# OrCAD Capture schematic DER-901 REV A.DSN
size Custom; title: DER-801 Rev B
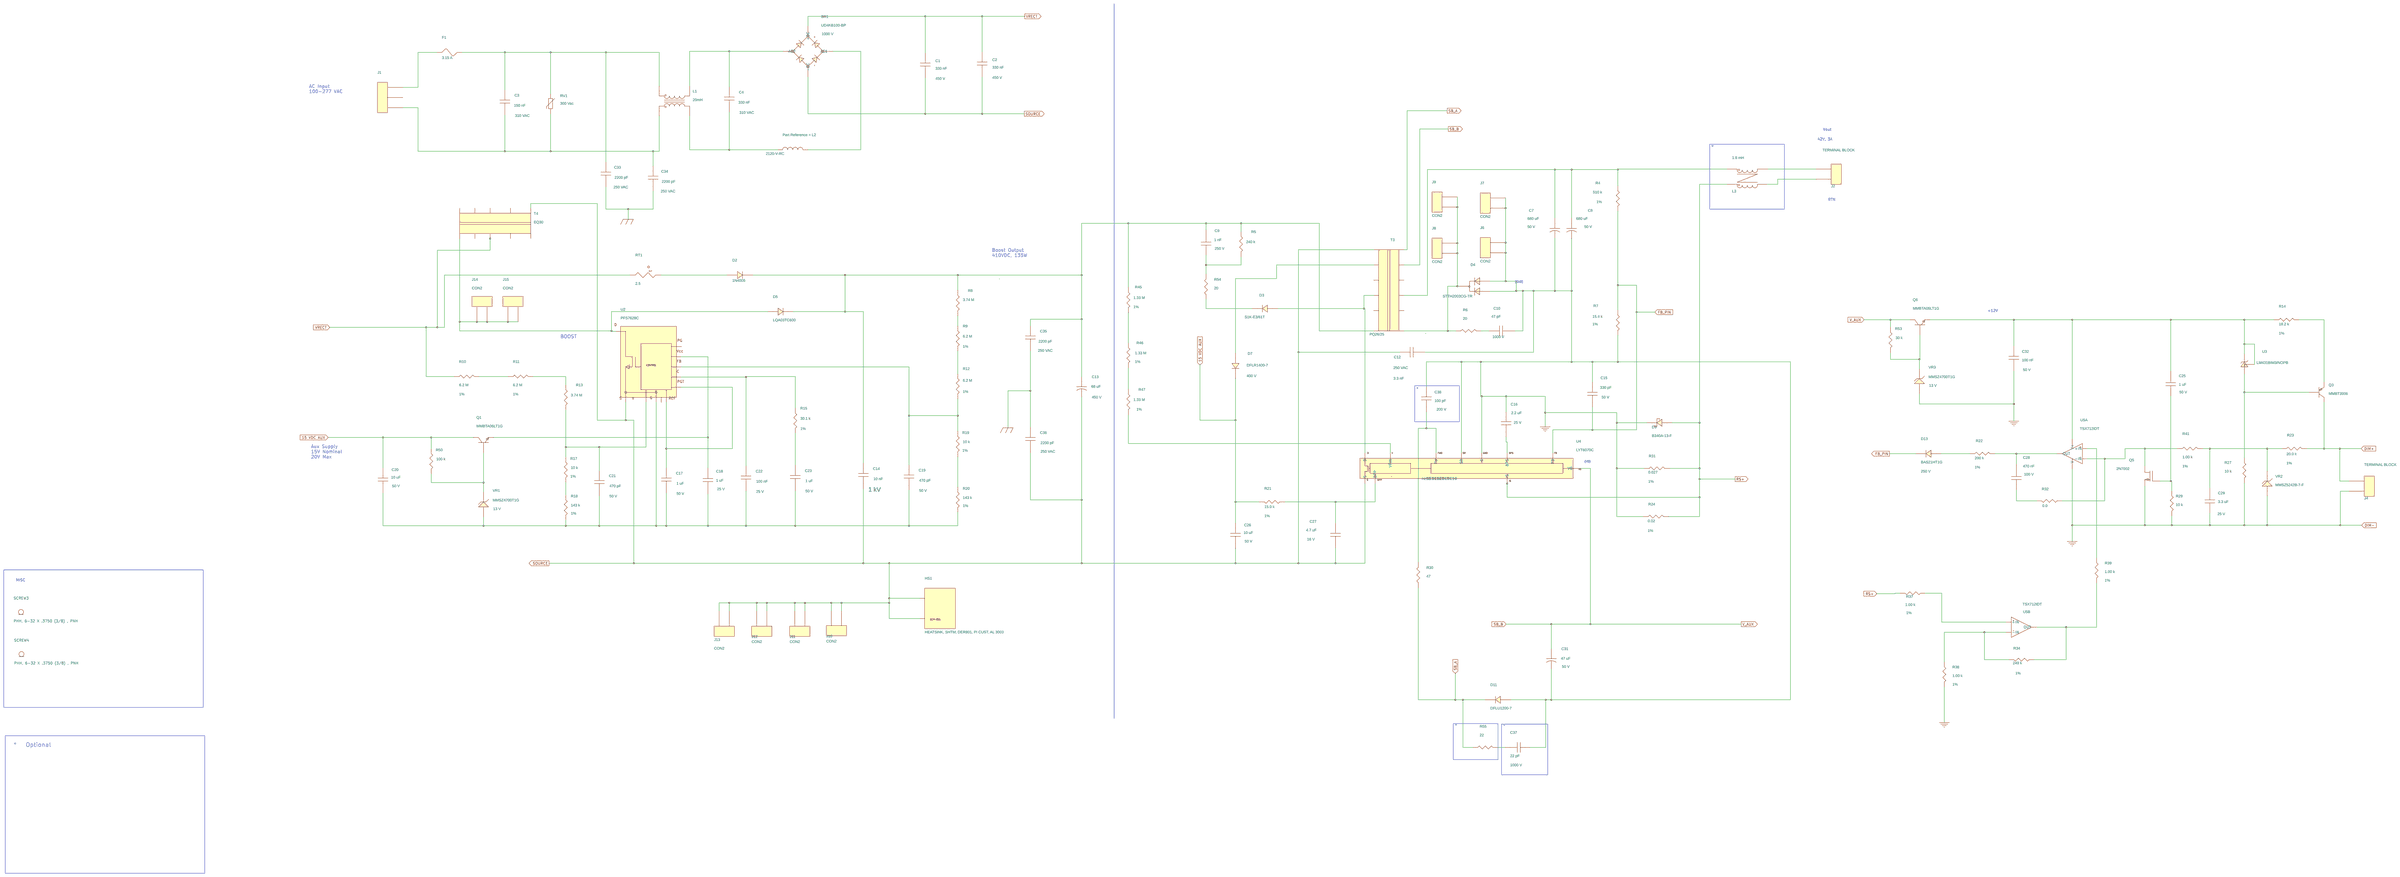
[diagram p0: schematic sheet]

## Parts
BR1  UD4KB100-BP  [pidaxbridgeD3K]
C1  330 nF  [pi_np_caprad512x299ls394d040]
C2  330 nF  [pi_np_caprad512x299ls394d040]
C3  150 nF  [pinpxcaprad720x240590040]
C4  330 nF  [pinpxcaprad710x315590046]
C7  680 uF  [pipolcapclyd500ls200040]
C8  680 uF  [pipolcapclyd500ls200040]
C9  1 nF  [pismc0805]
C10  47 pF  [pismc1206]
C12  3.3 nF  [pinpycaprad540x290ls400040]
C13  68 uF  [pipolcapclyd710ls300040]
C14  10 nF  [pi_np_cap250x200ls170d030]
C15  330 pF  [pismc0603]
C16  2.2 uF  [pismc1206]
C17  1 uF  [pismc0805]
C18  1 uF  [pismc0805]
C19  470 pF  [pismc0805]
C20  10 uF  [pismc1206]
C21  470 pF  [pismc0805]
C22  100 nF  [pismc0805]
C23  1 uF  [pismc0805]
C25  1 uF  [pismc0805]
C26  10 uF  [pismc1206]
C27  4.7 uF  [pismc0805]
C28  470 nF  [pismc1206]
C29  3.3 uF  [pismc0805]
C31  47 uF  [pipolcapcyld250ls100030]
C32  100 nF  [pismc0805]
C33  2200 pF  [pinpcaprad9p0D10p0LS030]
C34  2200 pF  [pinpcaprad9p0D10p0LS030]
C35  2200 pF  [pinpcaprad9p0D10p0LS030]
C36  2200 pF  [pinpcaprad9p0D10p0LS030]
C37  22 pF  [pismc0805]
C38  100 pF  [pismc0805]
D2  1N4006  [pidv200x110x040do41]
D3  S1K-E3/61T  [pismdo214ac12]
D4  STTH2003CG-TR  [pismdd2pak]
D5  LQA03TC600  [pidvt0220acreva]
D7  DFLR1400-7  [pismddflr120012]
D9  B340A-13-F  [pismdo214ac12]
D11  DFLU1200-7  [pismddflr120012]
D13  BAS21HT1G  [pismsod323]
F1  3.15 A  [pi_rst_microfuse]
HS1  HEATSINK, SHTM, DER801, PI CUST, AL 3003  [PI_HS_2P_DER801]
J1  TERMINAL BLOCK  [pi_term_block_3pin]
J2  TERMINAL BLOCK  [pi_term_block_2pin_ls200]
J4  TERMINAL BLOCK  [pi_term_block_2pin_ls200]
J6  CON2  [pi_conn_qc_tab_2pin_ls200]
J7  CON2  [pi_conn_qc_tab_2pin_ls200]
J8  CON2  [pi_conn_qc_tab_2pin_ls200]
J9  CON2  [pi_conn_qc_tab_2pin_ls200]
J10  CON2  [pi_conn_qc_tab_2pin_ls200]
J11  CON2  [pi_conn_qc_tab_2pin_ls200]
J12  CON2  [pi_conn_qc_tab_2pin_ls200]
J13  CON2  [pi_conn_qc_tab_2pin_ls200]
J14  CON2  [pi_conn_qc_tab_2pin_ls200]
J15  CON2  [pi_conn_qc_tab_2pin_ls200]
L1  20mH  [pi_ind_4p_690x512ls300x200d055]
L2  2120-V-RC  [pi_toroid_2p_350x860_ls330_d038]
L3  1.8 mH  [pi_coil_16x8_LS8x7p5]
Q1  MMBTA06LT1G  [pismsot23123_1]
Q3  MMBT3906  [pismsot23123_1]
Q5  2N7002  [pismsot23123_1]
Q6  MMBTA06LT1G  [pismsot23123_1]
R4  510 k  [pismr0805]
R5  240 k  [pismr1206]
R6  20  [pismr1206]
R7  15.4 k  [pismr0805]
R8  3.74 M  [pismr1206]
R9  6.2 M  [pismr1206]
R10  6.2 M  [pismr1206]
R11  6.2 M  [pismr1206]
R12  6.2 M  [pismr1206]
R13  3.74 M  [pismr1206]
R14  18.2 k  [pismr0805]
R15  30.1 k  [pismr0805]
R17  10 k  [pismr0805]
R18  143 k  [pismr0805]
R19  10 k  [pismr0805]
R20  143 k  [pismr0805]
R21  15.0 k  [pismr1206]
R22  200 k  [pismr0805]
R23  20.0 k  [pismr1206]
R24  0.02  [pismr0805]
R27  10 k  [pismr0805]
R29  10 k  [pismr0805]
R30  47  [pismr1206]
R31  0.027  [pismr1206]
R32  0.0  [pismr0805]
R34  249 k  [pismr0805]
R37  1.00 k  [pismr0805]
R38  1.00 k  [pismr0805]
R39  1.00 k  [pismr0805]
R41  1.00 k  [pismr0805]
R45  1.33 M  [pismr1206]
R46  1.33 M  [pismr1206]
R47  1.33 M  [pismr1206]
R50  100 k  [pismr0805]
R53  30 k  [pismr0805]
R54  20  [pismr1206]
R55  22  [pismr0805]
RT1  2.5  [pi_rad150x300ls200d030]
RV1  300 Vac  [pidisc350x225ls240x140040]
SCREW3  PHH, 6-32 X .3750 (3/8) , PNH
SCREW4  PHH, 6-32 X .3750 (3/8) , PNH
T3  PQ26/25  [pibobbinpq262512p]
T4  EQ30  [pi_bobbin_eq30_v_10p]
U2  PFS7628C  [PI_IC_INSOP24B]
U3  LM431BIM3/NOPB  [pismsot23123]
U4  LYT6070C  [pi_ic_insop_24d]
U5  TSX712IDT  [pismso8]  (sections A,B)
VR1  MMSZ4700T1G  [pi_sm_sod-123_12]
VR2  MMSZ5242B-7-F  [pi_sm_sod-123_12]
VR3  MMSZ4700T1G  [pi_sm_sod-123_12]

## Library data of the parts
BR1 = DISCRETE_BRIDGE_+~~-: ALT_SYMBOLS: pidaxbridgeD3K_horz; Disp_Voltage: 1000 V; FPLIST: pidaxbridgeD3K,pidaxbridgeD3K_horz; Part Number: 15-01213-00
C1 C2 = CAP_NP: ALT_SYMBOLS: pi_np_caprad512x299ls394d040_h; Disp_Voltage: 450 V; FPLIST: pi_np_caprad512x299ls394d040,pi_np_caprad512x299ls394d040_h; Part Number: 20-00973-00; Voltage: 450 V
C3 = CAP_NP: Disp_Voltage: 310 VAC; Part Number: 20-01052-00; Voltage: 310 VAC
C4 = CAP_NP: Disp_Voltage: 310 VAC; Part Number: 20-08604-00; Voltage: 310 VAC
C7 C8 = CAP_POL: ALT_SYMBOLS: pipolcapclyd500ls2000401000lh; COMPGROUP: 3; Disp_Voltage: 50 V; FPLIST: pipolcapclyd500ls200040,pipolcapclyd500ls2000401000lh; Part Number: 20-00710-00; Voltage: 50 V
C9 = CAP_NP: Disp_Voltage: 250 V; Part Number: 20-00736-00; Voltage: 250 V
C10 = CAP_NP: Disp_Voltage: 1000 V; PCB Editor PCBFP: pismc0603; Part Number: 20-08683-00; Voltage: 1000 V
C12 = CAP_NP: ALT_SYMBOLS: pinpycaprad540x290ls400040h; COMPGROUP: 3; Disp_Voltage: 250 VAC; FPLIST: pinpycaprad540x290ls400040,pinpycaprad540x290ls400040h; Part Number: 20-00377-00; Voltage: 250 VAC
C13 = CAP_POL: ALT_SYMBOLS: pi_cap_cly_d710_ls300_040_1000h; Disp_Voltage: 450 V; FPLIST: pipolcapclyd710ls300040,pi_cap_cly_d710_ls300_040_1000h; Part Number: 20-09153-00; Voltage: 450 V
C14 = CAP_NP: Disp_Voltage: 1 kV; Part Number: 20-00894-00; Voltage: 1 kV
C15 = CAP_NP: Disp_Voltage: 50 V; Part Number: 20-08676-00; Voltage: 50 V
C16 = CAP_NP: Disp_Voltage: 25 V; Part Number: 20-01034-00; Voltage: 25 V
C17 C23 = CAP_NP: Disp_Voltage: 50 V; Part Number: 20-09156-00; Voltage: 50 V
C18 = CAP_NP: Disp_Voltage: 25 V; Part Number: 20-09171-00; Voltage: 25 V
C19 C21 = CAP_NP: Disp_Voltage: 50 V; Part Number: 20-00205-00; Voltage: 50 V
C20 C26 = CAP_NP: ALT_SYMBOLS: pismc1206_1; Disp_Voltage: 50 V; FPLIST: pismc1206,pismc1206_1; Part Number: 20-08995-00; Voltage: 50 V
C22 = CAP_NP: Disp_Voltage: 25 V; Part Number: 20-08599-00; Voltage: 25 V
C25 = CAP_NP: Disp_Voltage: 50 V; Part Number: 20-09146-00; Voltage: 50 V
C27 = CAP_NP: Disp_Voltage: 16 V; Part Number: 20-09166-00; Voltage: 16 V
C28 = CAP_NP: Disp_Voltage: 100 V; Part Number: 20-00583-00; Voltage: 100 V
C29 = CAP_NP: Disp_Voltage: 25 V; Part Number: 20-01041-00; Voltage: 25 V
C31 = CAP_POL: ALT_SYMBOLS: pipolcapcyld250ls100030h; Disp_Voltage: 50 V; FPLIST: pipolcapcyld250ls100030,pipolcapcyld250ls100030h; Part Number: 20-01044-00; Voltage: 50 V
C32 = CAP_NP: Disp_Voltage: 50 V; Part Number: 20-00904-00; Voltage: 50 V
C33-C36 = CAP_NP: Disp_Voltage: 250 VAC; Part Number: 20-09158-00; Voltage: 250 VAC
C37 = CAP_NP: Disp_Voltage: 1000 V; PCB Editor PCBFP: pismc0603; Part Number: 20-08905-00; Voltage: 1000 V
C38 = CAP_NP: Disp_Voltage: 200 V; PCB Editor PCBFP: pismc0603; Part Number: 20-00760-00; Voltage: 200 V
D2 = DIODE: ALT_SYMBOLS: pidax475x125040do41,pidv200x110x040do41wbead,pidax390x125040do41; FPLIST: pidv200x110x040do41,pidax475x125040do41,pidv200x110x040do41wbead,pidax390x125040do41; Part Number: 15-00629-00
D3 = DIODE: Part Number: 15-01053-00
D4 = D_DUAL_CK_AKA: Part Number: 15-01586-00
D5 = DIODE: Part Number: 15-00834-00
D7 = DIODE: COMPGROUP: 1; Disp_Voltage: 400 V; Part Number: 15-01310-00
D9 = DIODE_SCHOTTKY: Part Number: 15-01172-00
D11 = DIODE: Part Number: 15-01043-00
D13 = DIODE: ALT_SYMBOLS: pismsod323_1; Disp_Voltage: 250 V; FPLIST: pismsod323,pismsod323_1; Part Number: 15-01247-00
F1 = FUSE: ALT_SYMBOLS: pirstmicrofusehoz; FPLIST: pi_rst_microfuse,pirstmicrofusehoz; Part Number: 40-00020-00
HS1 = hs_2P_DER801: Part Number: 61-00245-00
J1 = CON3: Part Number: 35-00175-00
J2 J4 = CON2: Part Number: 35-00277-00
J6-J15 = CON2: Part Number: 35-00281-00
L1 = INDUCTOR_4P_revD: ALT_SYMBOLS: pi_4p_700x400d055_horiz; FPLIST: pi_ind_4p_690x512ls300x200d055,pi_4p_700x400d055_horiz; Part Number: 30-04099-00
L2 = INDUCTOR: ALT_SYMBOLS: pi_2p_700x400d055_horiz; FPLIST: pi_toroid_2p_350x860_ls330_d038,pi_2p_700x400d055_horiz; Part Number: 32-00224-00
L3 = TORRID_4P_14_23: Part Number: 32-00375-00
Q1 Q6 = NPN_BEC: Part Number: 55-00072-00
Q3 = PNP_BEC: Part Number: 55-00049-00
Q5 = FET_N_GSD: Part Number: 50-00103-00
R4 = R: Disp_Tol: 1%; Part Number: 05-03469-00
R5 = R: Part Number: 05-01409-00
R6 R54 = R: Part Number: 05-01311-00
R7 = R: Disp_Tol: 1%; Part Number: 05-00702-00
R8 R13 = R: Part Number: 05-05572-00
R9-R12 = R: Disp_Tol: 1%; Part Number: 05-05567-00
R14 = R: Disp_Tol: 1%; Part Number: 05-00709-00
R15 = R: Disp_Tol: 1%; Part Number: 05-00730-00
R17 R19 = R: Disp_Tol: 1%; Part Number: 05-00684-00
R18 R20 = R: Disp_Tol: 1%; Part Number: 05-00795-00
R21 = R: Disp_Tol: 1%; Part Number: 05-00306-00
R22 = R: Disp_Tol: 1%; Part Number: 05-00809-00
R23 = R: Disp_Tol: 1%; Part Number: 05-00318-00
R24 = R: Disp_Tol: 1%; Part Number: 05-05450-00
R27 R29 = R: Part Number: 05-01543-00
R30 = R: Part Number: 05-01320-00
R31 = R: Disp_Tol: 1%; Part Number: 05-06531-00
R32 = R: ALT_SYMBOLS: pismr0805_1; FPLIST: pismr0805,pismr0805_1; Part Number: 05-03159-00
R34 = R: Disp_Tol: 1%; Part Number: 05-00818-00
R37-R39 R41 = R: Disp_Tol: 1%; Part Number: 05-03310-00
R45-R47 = R: Disp_Tol: 1%; Part Number: 05-05444-00
R50 = R: Part Number: 05-01567-00
R53 = R: Part Number: 05-01554-00
R55 = R: Part Number: 05-01479-00
RT1 = THERMISTOR: ALT_SYMBOLS: pirad400x300ls200040_h; FPLIST: pi_rad150x300ls200d030,pirad400x300ls200040_h; Part Number: 90-00040-00
RV1 = VARISTOR: Part Number: 85-00031-00
SCREW3 SCREW4 = SCR_6-32: Part Number: 75-00009-00
T3 = BPQ26_25_12P_GENERIC: Part Number: 25-00055-00
T4 = BEQ30_10P_GENERIC: Part Number: 25-00074-00
U2 = HIPERPFS-4-inSOP24B_0: Part Number: 10-01069-00
U3 = TL431_SOT-23_CAR: Part Number: 45-00232-00
U4 = LYT6: Part Number: 10-01225-00
U5 = TSX712IDT: Part Number: 45-00514-00
VR1 VR3 = DIODE_ZENER: Disp_Voltage: 13 V; Part Number: 15-01046-00
VR2 = DIODE_ZENER: Part Number: 15-01090-00

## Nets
GND: C7.2 C8.2 C10.2 C12.2 C15.1 C16.1 C29.1 C31.2 C32.2 C37.1 C38.1 D4.1(A1) D4.3(A2) D9.1 D11.2 J4.1 J6.1 J6.2 J7.1 J7.2 Q5.2(S) R7.2 R24.1 R27.2 R29.2 R31.1 R38.2 U4.2(G) U4.5(SR) U5.4(V-) VR2.2 VR3.2
GND_EARTH: C33.2 C34.2 C35.2 C36.1
15 VDC AUX: C20.1 C26.1 D7.1 Q1.3(COLLECTOR) R21.1 R50.1
DIM+: J4.2 Q3.3(COLLECTOR) R23.2
FB_PIN: C15.2 D13.1 R4.2 R7.1 U4.3(FB)
NC8: U4.8(NC8)
NC9: U4.9(NC9)
NC10: U4.10(NC10)
NC11: U4.11(NC11)
NC12: U4.12(NC12)
NC15: U4.15(nc15)
RS+: D9.2 L3.2 R24.2 R31.2 R37.2 U4.1(IS)
SB_A: D11.1 R30.1 R55.2 T3.7
SB_B: C31.1 Q6.3(COLLECTOR) R53.1 T3.8 U4.6(VO)
SOURCE: BR1.4(-DC) C1.2 C2.2 C12.1 C13.2 C14.2 C26.2 C27.2 C36.2 HS1.1 HS1.2 J10.1 J10.2 J11.1 J11.2 J12.1 J12.2 J13.1 J13.2 T3.6 T4.6 U2.24(S) U4.16(S)
VRECT: BR1.1(+DC) C1.1 C2.1 R10.1 RT1.1 T4.3
N11474046: F1.1 J1.3
N11474062: C3.1 C33.1 F1.2 L1.4 RV1.1
N11474114: BR1.3(AC2) C4.1 L1.3
N11474138: BR1.2(AC1) L2.2
N11474236: C3.2 C34.1 J1.1 L1.1 RV1.2
N11474420: C4.2 L1.2 L2.1
N11475153: C9.2 C13.1 C14.1 C35.1 D2.1 D5.1 R5.1 R8.1 R45.1 T3.1
N11476179: D5.2 J14.1 J14.2 J15.1 J15.2 T4.1 U2.16(D)
N11479125: C18.1 Q1.2(EMITTER) U2.1(Vcc)
N11479237: C17.2 C18.2 C19.2 C20.2 C21.2 C22.2 C23.2 R18.2 R20.2 U2.2(G) VR1.2
N11479555: C22.1 R15.1 U2.5(C)
N11479611: C23.1 R15.2
N11480020: C21.1 R13.2 R17.1 U2.4(V)
N11480864: R10.2 R11.1
N11480868: R11.2 R13.1
N11482311: R8.2 R9.1
N11482333: R9.2 R12.2
N11482355: C19.1 R12.1 R19.1 U2.6(FB)
N11498787: C7.1 C8.1 L3.1 R4.1 T3.10
N11498945: C9.1 R5.2 R54.2
N11499171: D4.2(Cathode) J8.1 J8.2 J9.1 J9.2 R6.2 T3.12
N11499175: C10.1 R6.1
N11499225: D3.2 T3.3 U4.24(D)
N11499609: C38.2 R30.2 U4.7(FW)
N11499655: C16.2 U4.4(BPS)
N11499799: C27.1 R21.2 U4.14(BPP)
N11939314: R19.2 R20.1
N11966145: D7.2 T3.5
N11977822: C17.1 U2.3(REF) U2.8(PGT)
N11995900: Q1.1(BASE) R50.2 VR1.1
N12000412: R17.2 R18.1
N12016680: R45.2 R46.1
N12017060: R46.2 R47.1
N12033400: C25.2 C32.1 Q6.2(EMITTER) R14.1 U3.1(C) U3.3(VREF) U5.8(V+)
N12033444: Q3.2(EMITTER) R14.2
N12033508: Q3.1(BASE) R27.1 U3.2(A)
N12033698: R39.1 U5.3(+IN)
N12033710: C29.2 R23.1 R41.2 VR2.1
N12033758: D13.2 R22.1
N12033766: C28.2 R22.2 U5.1(OUT)
N12033774: Q5.3(D) R32.1 R41.1 U5.2(-IN)
N12033856: C25.1 Q5.1(G) R29.1
N12033928: C28.1 R32.2
N12034132: R34.2 R38.1 U5.6(-IN)
N12034136: R34.1 R39.2 U5.7(OUT)
N12052159: Q6.1(BASE) R53.2 VR3.1
N12053445: D3.1 R54.1
N12080403: R37.1 U5.5(+IN)
N12174734: C37.2 R55.1
N12244813: D2.2 RT1.2
N12258356: R47.2 U4.13(VPIN)
N12288102: J2.2 L3.4
N12288115: J2.1 L3.3

Not connected (* = marked no-connect by the designer): J1 2; T3 2 4 9 11; T4 2 4 5 7 8 9 10; U2 7(PG) 12(G12)

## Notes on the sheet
- AC Input
  100-277 VAC
- Vout
- 42V, 3A
- *
- RTN
- Boost Output
  410VDC, 135W
- (GND)
- +12V
- BOOST
- *
- Aux Supply
  15V Nominal
  20V Max
- (VO)
- MISC
- *
- *
- *
- Optional
